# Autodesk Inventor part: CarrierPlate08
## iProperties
Created: 2008-02
Part Number: CarrierPlate08
Document SubType Name: Modeling
Designer: grh
Density: 1 g/cm^3
Author: grh
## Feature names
1. Extrusion1
